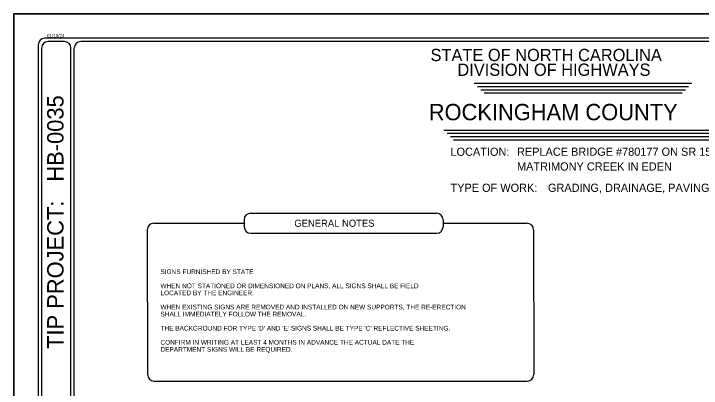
# Model space of a CAD drawing. Extents: x 1359317 to 1361345, y 1001522 to 1002524.
# Drawn here: x 1359317 to 1360274, y 1002003 to 1002524 of the extents above; entities that cross this region are included whole.
import ezdxf

# ---------------------------------------------------------------- set-up
doc = ezdxf.new("R2010")
doc.units = 0
for name, color, linetype in [('Sheet Plot Border Outside CELL', 7, 'Continuous'), ('Sheet_Data_Field_CELL', 7, 'Continuous'), ('Sheet_Title_CELL', 7, 'Continuous'), ('Sheet_Title_Data_Points_CELL', 7, 'Continuous'), ('Text', 7, 'Continuous'), ('z - Construction', 7, 'Continuous')]:
    doc.layers.add(name, color=color, linetype=linetype)

msp = doc.modelspace()

# ---------------------------------------------------------------- linework, layer by layer
at = {"layer": 'Sheet Plot Border Outside CELL'}
msp.add_lwpolyline([(1359316.74, 1002523.7), (1360865.01, 1002523.7), (1360865.01, 1001521.88), (1359316.74, 1001521.88)], close=True, dxfattribs=at)
at = {"layer": 'Sheet_Title_CELL'}
for p, q in [((1360821.75, 1002489.54), (1359360, 1002489.54)), ((1360817.19, 1002484.93), (1359410.09, 1002484.93)), ((1359350.9, 1002480.44), (1359350.9, 1001565.14)), ((1359355.46, 1002475.83), (1359355.45, 1001569.64)), ((1359396.43, 1001569.64), (1359396.43, 1002475.83)), ((1359401, 1001569.63), (1359400.99, 1002475.82)), ((1359958.33, 1002427.12), (1360261.38, 1002427.14)), ((1359962.89, 1002422.58), (1360256.83, 1002422.57)), ((1359967.44, 1002418.02), (1360252.28, 1002418.03)), ((1359971.99, 1002413.46), (1360247.72, 1002413.47)), ((1359915.85, 1002361.93), (1360303.83, 1002361.91)), ((1359920.4, 1002357.37), (1360299.27, 1002357.36)), ((1359924.95, 1002352.81), (1360294.72, 1002352.82)), ((1359929.51, 1002348.26), (1360290.16, 1002348.25)), ((1359646.69, 1002246.12), (1359905.78, 1002246.12)), ((1359637.59, 1002237.03), (1359637.79, 1002227.28)), ((1359914.88, 1002237.07), (1359914.87, 1002227.26)), ((1359511.88, 1002232.16), (1359637.69, 1002232.15)), ((1359914.87, 1002232.15), (1360031.86, 1002232.15)), ((1359502.79, 1002223.06), (1359503.08, 1002021.72)), ((1359646.88, 1002218.18), (1359905.78, 1002218.17)), ((1360040.95, 1002223.06), (1360041.17, 1002021.7)), ((1359512.17, 1002012.63), (1360032.07, 1002012.59))]:
    msp.add_line(p, q, dxfattribs=at)
msp.add_lwpolyline([(1359387.33, 1002484.97), (1359364.56, 1002484.98)], dxfattribs=at)
for centre, radius, start, end in [((1359360, 1002480.44), 9.11, 90, 180), ((1359364.56, 1002475.87), 9.11, 90, 180), ((1359387.33, 1002475.87), 9.11, 0, 90), ((1359410.09, 1002475.82), 9.11, 90, 180), ((1359646.69, 1002237.03), 9.09, 90, 180), ((1359905.79, 1002237.07), 9.09, 0, 90), ((1359511.88, 1002223.06), 9.09, 90, 180), ((1359646.88, 1002227.28), 9.09, 180, 270), ((1359905.78, 1002227.26), 9.09, 270, 360), ((1360031.86, 1002223.06), 9.09, 0.00114, 90), ((1359512.17, 1002021.72), 9.09, 180, 270), ((1360032.07, 1002021.68), 9.09, 270, 0)]:
    msp.add_arc(centre, radius, start, end, dxfattribs=at)
at = {"layer": 'Sheet_Title_Data_Points_CELL'}
msp.add_line((1360111.25, 1002375.5), (1360111.25, 1002375.5), dxfattribs=at)
at = {"layer": 'z - Construction'}
for p, q in [((1360865.01, 1002523.7), (1359316.74, 1002523.7)), ((1359316.74, 1002523.7), (1359316.74, 1001521.88))]:
    msp.add_line(p, q, dxfattribs=at)

# ---------------------------------------------------------------- texts
at = {"layer": 'Sheet_Data_Field_CELL'}
for s, height, p in [('ROCKINGHAM COUNTY', 22.7687, (1359894.88, 1002375.5)), ('REPLACE BRIDGE #780177 ON SR 1535 (PRICE ROAD) OVER', 11.3844, (1360017.8, 1002326.04)), ('MATRIMONY CREEK IN EDEN', 11.3844, (1360017.8, 1002305.55)), ('GRADING, DRAINAGE, PAVING & STRUCTURE', 11.3844, (1360060.92, 1002275.88))]:
    msp.add_text(s, height=height, dxfattribs=at).set_placement(p)
at = {"layer": 'Sheet_Title_CELL'}
for s, height, p in [('01/16/24', 4.554, (1359363, 1002491.03)), ('STATE OF NORTH CAROLINA', 17.0764, (1359897.31, 1002457.8)), ('DIVISION OF HIGHWAYS', 17.0764, (1359934.76, 1002437.31)), ('LOCATION: ', 11.384, (1359925.14, 1002326)), ('TYPE OF WORK:', 11.3844, (1359925.14, 1002275.88))]:
    msp.add_text(s, height=height, dxfattribs=at).set_placement(p)
for s, height, p in [('HB-0035', 22.769, (1359386.06, 1002290.09)), ('TIP PROJECT:', 22.7686, (1359386.06, 1002057.33))]:
    msp.add_text(s, height=height, rotation=90, dxfattribs=at).set_placement(p)
at = {"layer": 'Text'}
msp.add_text('GENERAL NOTES', height=9.8184, dxfattribs=at).set_placement((1359707.65, 1002227.24))
for s, p in [('SIGNS FURNISHED BY STATE', (1359521.13, 1002161.41)), ('WHEN NOT STATIONED OR DIMENSIONED ON PLANS, ALL SIGNS SHALL BE FIELD ', (1359521.13, 1002141.77)), ('LOCATED BY THE ENGINEER.', (1359521.13, 1002131.96)), ('WHEN EXISTING SIGNS ARE REMOVED AND INSTALLED ON NEW SUPPORTS, THE RE-ERECTION', (1359521.13, 1002112.32)), ('SHALL IMMEDIATELY FOLLOW THE REMOVAL.', (1359521.13, 1002102.5)), ("THE BACKGROUND FOR TYPE 'D' AND 'E' SIGNS SHALL BE TYPE 'C' REFLECTIVE SHEETING.", (1359521.13, 1002082.86)), ('CONFIRM IN WRITING AT LEAST 4 MONTHS IN ADVANCE THE ACTUAL DATE THE ', (1359521.13, 1002063.23)), ('DEPARTMENT SIGNS WILL BE REQUIRED.', (1359521.13, 1002053.41))]:
    msp.add_text(s, height=6.5456, rotation=359.99749, dxfattribs=at).set_placement(p)

doc.saveas('drawing.dxf')
